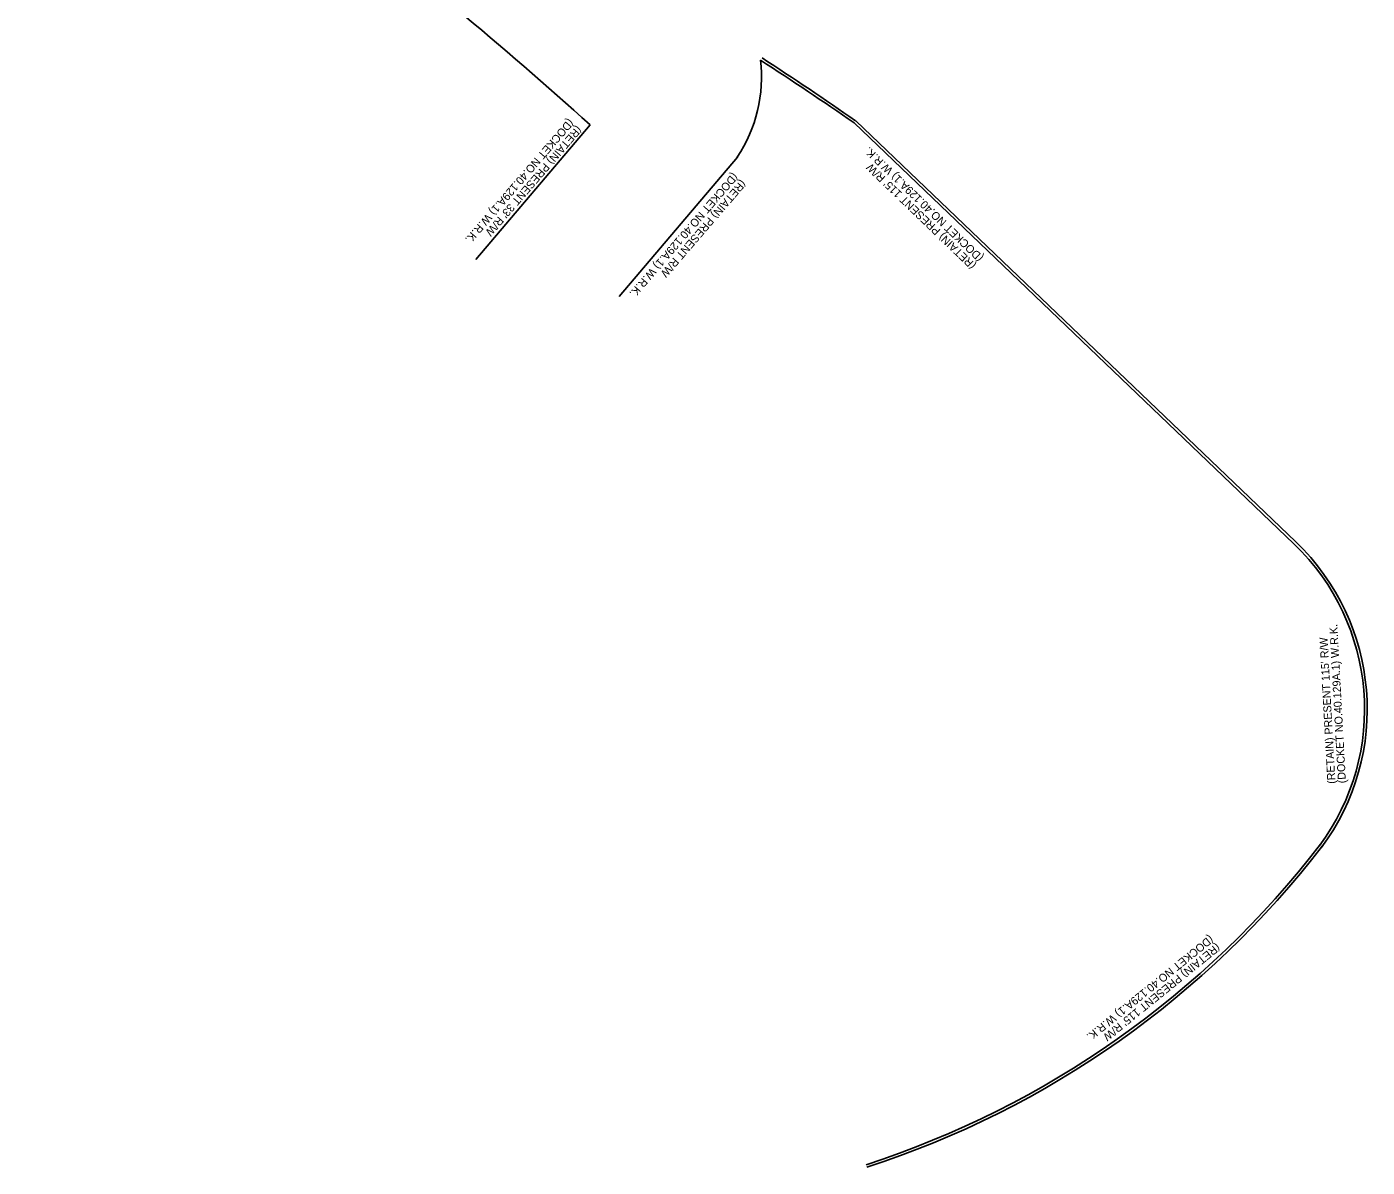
# Model space of a CAD drawing. Extents: x 2004008 to 2024436, y 806921 to 864820.
# Drawn here: x 2021703 to 2022708, y 813493 to 814347 of the extents above; entities that cross this region are included whole.
import ezdxf

# ---------------------------------------------------------------- set-up
doc = ezdxf.new("R2010")
doc.units = 0
for name, color, linetype in [('RD_PD_DR_ErosCtrl', 7, 'Continuous'), ('RD_PD_Final_LnLine', 7, 'Continuous'), ('RD_PD_MedBWall', 7, 'Continuous')]:
    doc.layers.add(name, color=color, linetype=linetype)

msp = doc.modelspace()

# ---------------------------------------------------------------- linework, layer by layer
at = {"layer": 'RD_PD_Final_LnLine'}
for p, q in [((2022039.6, 814172.8), (2022125.3, 814273.7)), ((2022652.7, 813959.8), (2022323.1, 814275.2)), ((2022147, 814145.2), (2022235.7, 814249.6))]:
    msp.add_line(p, q, dxfattribs=at)
for centre, radius, start, end in [((2020043.9, 811970), 3104.7, 47.9016, 57.6957), ((2022145, 814309.7), 108.7, 326.4451, 6.6045), ((2020793.4, 812069.9), 2683.9, 55.2536, 57.0537), ((2022534.2, 813835.9), 171.5, 323.2863, 46.2689), ((2022115.3, 814164), 703.5, 287.9445, 322.4039)]:
    msp.add_arc(centre, radius, start, end, dxfattribs=at)
at = {"layer": 'RD_PD_MedBWall'}
msp.add_line((2022654.1, 813961.3), (2022324.5, 814276.7), dxfattribs=at)
for centre, radius, start, end in [((2020793.4, 812069.9), 2685.9, 55.2536, 57.0537), ((2022534.2, 813835.9), 173.5, 323.2863, 46.2689), ((2022115.3, 814164), 705.5, 287.9445, 322.4039)]:
    msp.add_arc(centre, radius, start, end, dxfattribs=at)

# ---------------------------------------------------------------- texts
at = {"layer": 'RD_PD_DR_ErosCtrl'}
for s, rotation, p in [('(DOCKET NO.40.129A.1) W.R.K.', 229.2819, (2022109.1, 814278.8)), ("(RETAIN) PRESENT 33' R/W", 229.2819, (2022115.1, 814273.6)), ('(DOCKET NO.40.129A.1) W.R.K.', 136.1154, (2022420.5, 814174.9)), ("(RETAIN) PRESENT 115' R/W", 136.1154, (2022415, 814169.2)), ('(DOCKET NO.40.129A.1) W.R.K.', 229.2819, (2022232.2, 814238.3)), ('(RETAIN) PRESENT R/W', 229.2819, (2022238.2, 814233.1)), ('(DOCKET NO.40.129A.1) W.R.K.', 93.1296, (2022691.8, 813780.6)), ("(RETAIN) PRESENT 115' R/W", 93.1296, (2022683.9, 813780.2)), ('(DOCKET NO.40.129A.1) W.R.K.', 219.0735, (2022589.5, 813667)), ("(RETAIN) PRESENT 115' R/W", 219.0735, (2022594.5, 813660.9))]:
    msp.add_text(s, height=6, rotation=rotation, dxfattribs=at).set_placement(p)

doc.saveas('drawing.dxf')
